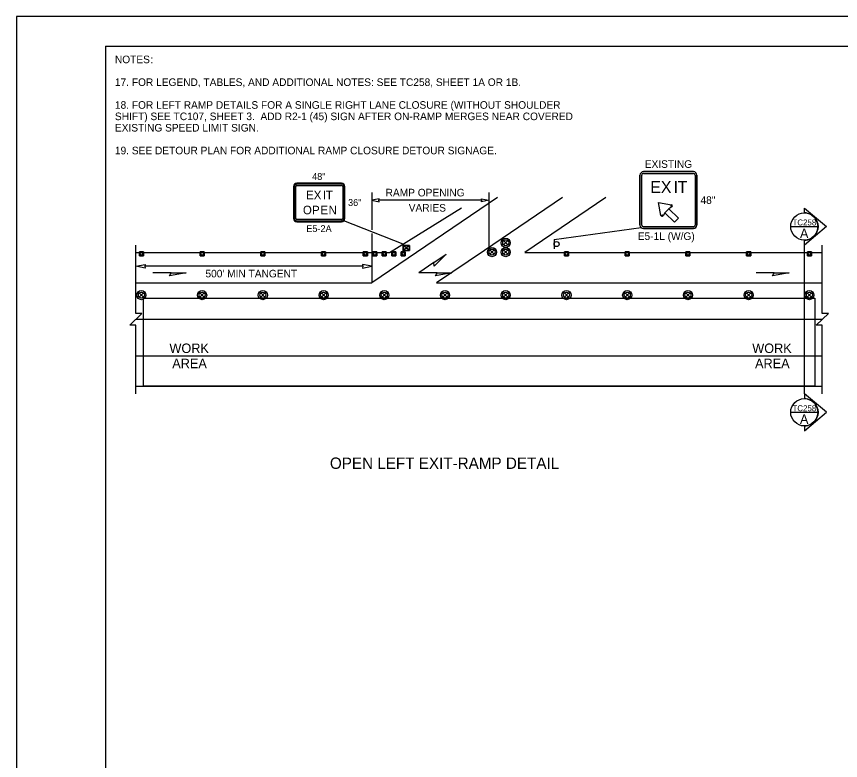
# Model space of a CAD drawing. Extents: x 99999 to 100116, y 99995 to 100013.
# Drawn here: x 100079.06 to 100087.75, y 100002.85 to 100010.69 of the extents above; entities that cross this region are included whole.
import ezdxf

# ---------------------------------------------------------------- set-up
doc = ezdxf.new("R2010")
doc.units = 0
for name, color, linetype in [('RD_MK_LineEdgeYellow', 7, 'Continuous'), ('RD_MK_LineLane', 7, 'Continuous'), ('SH_DE_DetailHeading2Text', 7, 'Continuous'), ('SH_GI_GeneralNotesBodyText', 7, 'Continuous'), ('SH_GI_PlotLimits', 7, 'Continuous'), ('SH_GI_SectionCut', 7, 'Continuous'), ('SH_GI_SheetBorder', 7, 'Continuous'), ('TR_SN_ConstructionSigns', 7, 'Continuous'), ('TR_WZ_PortableSignMount5ftMinBlk-Org', 7, 'Continuous'), ('TR_WZ_TrafficCone', 7, 'Continuous'), ('TR_WZ_TrafficSafetyDrum', 7, 'Continuous'), ('TR_WZ_WorkAreaLabel', 7, 'Continuous'), ('TR_WZ_WorkZoneDetails', 7, 'Continuous'), ('TR_WZ_WorkZoneTextCurrent', 7, 'Continuous')]:
    doc.layers.add(name, color=color, linetype=linetype)

msp = doc.modelspace()

# ---------------------------------------------------------------- linework, layer by layer
at = {"layer": 'RD_MK_LineEdgeYellow'}
for p, q in [((100084.1333, 100008.7784), (100082.8064, 100007.8789)), ((100080.32, 100007.8789), (100082.8064, 100007.8789)), ((100084.4209, 100007.8789), (100087.555, 100007.8789)), ((100080.32, 100007.1109), (100087.555, 100007.1109))]:
    msp.add_line(p, q, dxfattribs=at)
at = {"layer": 'RD_MK_LineLane'}
msp.add_lwpolyline([(100087.555, 100007.4949), (100080.32, 100007.4949)], dxfattribs=at)
at = {"layer": 'SH_GI_PlotLimits'}
msp.add_lwpolyline([(100079.0625, 99999.6875), (100096.0625, 99999.6875), (100096.0625, 100010.6875), (100079.0625, 100010.6875)], close=True, dxfattribs=at)
at = {"layer": 'SH_GI_SectionCut'}
for p, q in [((100087.3657, 100008.6178), (100087.3657, 100008.6687)), ((100087.3657, 100008.6687), (100087.5983, 100008.4738)), ((100087.5983, 100008.4738), (100087.3657, 100008.2789)), ((100087.3657, 100008.2789), (100087.3657, 100008.3298)), ((100087.3657, 100006.7109), (100087.3657, 100008.2789)), ((100087.3657, 100006.7109), (100087.3657, 100006.66)), ((100087.5983, 100006.516), (100087.3657, 100006.7109)), ((100087.3657, 100006.3211), (100087.5983, 100006.516)), ((100087.3657, 100006.372), (100087.3657, 100006.3211))]:
    msp.add_line(p, q, dxfattribs=at)
for points in [[(100087.2217, 100008.4738), (100087.5097, 100008.4738)], [(100087.2217, 100006.516), (100087.5097, 100006.516)]]:
    msp.add_lwpolyline(points, dxfattribs=at)
for centre in [(100087.3657, 100008.4738), (100087.3657, 100006.516)]:
    msp.add_circle(centre, 0.144, dxfattribs=at)
for centre in [(100087.3657, 100008.4738), (100087.3657, 100006.516)]:
    msp.add_arc(centre, 0.144, 269.99779, 90.00221, dxfattribs=at)
at = {"layer": 'SH_GI_SheetBorder'}
for q in [(100080, 100000), (100095.75, 100010.375)]:
    msp.add_line((100080, 100010.375), q, dxfattribs=at)
at = {"layer": 'TR_SN_ConstructionSigns'}
for p, q in [((100085.6712, 100009.0522), (100086.1962, 100009.0522)), ((100086.1962, 100009.0522), (100085.6712, 100009.0522)), ((100086.1962, 100009.0522), (100085.6712, 100009.0522)), ((100086.1962, 100009.0522), (100085.6712, 100009.0522)), ((100086.1962, 100009.0522), (100085.6712, 100009.0522)), ((100085.6712, 100009.0335), (100086.1962, 100009.0335)), ((100086.1962, 100009.0522), (100086.1962, 100009.0522)), ((100085.6337, 100008.4897), (100085.6337, 100009.0147)), ((100085.6337, 100009.0147), (100085.6337, 100009.0147)), ((100085.6337, 100009.0147), (100085.6337, 100008.4897)), ((100085.6337, 100009.0147), (100085.6337, 100008.4897)), ((100085.6337, 100009.0147), (100085.6337, 100008.4897)), ((100085.6337, 100009.0147), (100085.6337, 100008.4897)), ((100085.6525, 100008.4897), (100085.6525, 100009.0147)), ((100086.215, 100009.0147), (100086.215, 100008.4897)), ((100086.2337, 100009.0147), (100086.2337, 100008.4897)), ((100086.2337, 100008.4897), (100086.2337, 100009.0147)), ((100086.2337, 100008.4897), (100086.2337, 100009.0147)), ((100086.2337, 100008.4897), (100086.2337, 100009.0147)), ((100086.2337, 100008.4897), (100086.2337, 100009.0147)), ((100081.983, 100008.8955), (100081.983, 100008.558)), ((100081.9914, 100008.8955), (100081.9914, 100008.558)), ((100082.0055, 100008.558), (100082.0055, 100008.8955)), ((100082.4893, 100008.9292), (100082.0168, 100008.9292)), ((100082.4893, 100008.9208), (100082.0168, 100008.9208)), ((100082.0168, 100008.9067), (100082.4893, 100008.9067)), ((100082.5005, 100008.8955), (100082.5005, 100008.558)), ((100082.5146, 100008.558), (100082.5146, 100008.8955)), ((100082.523, 100008.558), (100082.523, 100008.8955)), ((100085.8293, 100008.7277), (100085.9652, 100008.7029)), ((100085.8541, 100008.5918), (100085.8293, 100008.7277)), ((100085.9688, 100008.68), (100085.9376, 100008.6614)), ((100085.9652, 100008.7029), (100085.9624, 100008.6907)), ((100085.9624, 100008.6907), (100085.9652, 100008.7029)), ((100085.9624, 100008.6907), (100085.9688, 100008.68)), ((100085.9688, 100008.68), (100085.9624, 100008.6907)), ((100085.8663, 100008.5946), (100085.8541, 100008.5918)), ((100085.8541, 100008.5918), (100085.8663, 100008.5946)), ((100085.8771, 100008.5882), (100085.8663, 100008.5946)), ((100085.8663, 100008.5946), (100085.8771, 100008.5882)), ((100085.8956, 100008.6195), (100085.8771, 100008.5882)), ((100085.8956, 100008.6195), (100085.9376, 100008.6614)), ((100085.9376, 100008.6614), (100085.8956, 100008.6195)), ((100085.9961, 100008.5189), (100085.8956, 100008.6195)), ((100085.9376, 100008.6614), (100086.0381, 100008.5609)), ((100082.4893, 100008.5467), (100082.0168, 100008.5467)), ((100082.0168, 100008.5327), (100082.4893, 100008.5327)), ((100082.0168, 100008.5242), (100082.4893, 100008.5242)), ((100086.0381, 100008.5609), (100085.9961, 100008.5189)), ((100086.1962, 100008.471), (100085.6712, 100008.471)), ((100086.1962, 100008.4522), (100085.6712, 100008.4522)), ((100085.6712, 100008.4522), (100085.6712, 100008.4522)), ((100085.6712, 100008.4522), (100086.1962, 100008.4522)), ((100085.6712, 100008.4522), (100086.1962, 100008.4522)), ((100085.6712, 100008.4522), (100086.1962, 100008.4522)), ((100086.2337, 100008.4897), (100086.2337, 100008.4897))]:
    msp.add_line(p, q, dxfattribs=at)
for points in [[(100085.6712, 100008.4522), (100085.6712, 100008.4522)], [(100085.6712, 100008.4522), (100086.1962, 100008.4522), (100086.1962, 100008.4522)]]:
    msp.add_lwpolyline(points, dxfattribs=at)
for centre, radius, start, end in [((100085.6712, 100009.0147), 0.0375, 90, 180.00001), ((100085.6712, 100009.0147), 0.0375, 90, 180), ((100085.6712, 100009.0147), 0.0375, 90, 180), ((100085.6712, 100009.0147), 0.0375, 90, 180), ((100085.6712, 100009.0147), 0.0375, 90, 180), ((100085.6712, 100009.0147), 0.0187, 90, 180.00001), ((100086.1962, 100009.0147), 0.0375, 0, 90), ((100086.1962, 100009.0147), 0.0375, 0, 90), ((100086.1962, 100009.0147), 0.0375, 0, 90), ((100086.1962, 100009.0147), 0.0375, 0, 90), ((100086.1962, 100009.0147), 0.0375, 0, 90), ((100086.1962, 100009.0147), 0.0187, 0, 90), ((100082.0168, 100008.8955), 0.0338, 90, 180), ((100082.0168, 100008.8955), 0.0253, 90, 180.00001), ((100082.0168, 100008.8955), 0.0112, 90, 180.00001), ((100082.4893, 100008.8955), 0.0338, 360, 90), ((100082.4893, 100008.8955), 0.0253, 360, 90), ((100082.4893, 100008.8955), 0.0112, 360, 90), ((100085.9624, 100008.6907), 0.0125, 300.67412, 77.22876), ((100085.8663, 100008.5946), 0.0125, 192.77123, 329.32586), ((100082.0168, 100008.558), 0.0338, 180, 270.00001), ((100082.0168, 100008.558), 0.0253, 180.00001, 270), ((100082.0168, 100008.558), 0.0112, 180.00001, 270), ((100082.4893, 100008.558), 0.0338, 270.00001, 0.00001), ((100082.4893, 100008.558), 0.0253, 270, 0.00001), ((100082.4893, 100008.558), 0.0112, 270, 0.00001), ((100085.6712, 100008.4897), 0.0375, 180.00001, 270), ((100085.6712, 100008.4897), 0.0375, 180, 270.00001), ((100085.6712, 100008.4897), 0.0375, 180, 270.00001), ((100085.6712, 100008.4897), 0.0375, 180, 270), ((100085.6712, 100008.4897), 0.0375, 180, 270.00001), ((100085.6712, 100008.4897), 0.0187, 180.00001, 270), ((100086.1962, 100008.4897), 0.0375, 270, 0.00001), ((100086.1962, 100008.4897), 0.0375, 270.00001, 0.00001), ((100086.1962, 100008.4897), 0.0375, 270.00001, 0.00001), ((100086.1962, 100008.4897), 0.0375, 270.00001, 0.00001), ((100086.1962, 100008.4897), 0.0187, 270, 0.00001), ((100086.1962, 100008.4897), 0.0375, 270.00001, 0.00001)]:
    msp.add_arc(centre, radius, start, end, dxfattribs=at)
at = {"layer": 'TR_WZ_PortableSignMount5ftMinBlk-Org'}
for p, q in [((100083.1389, 100008.2069), (100083.1389, 100008.2869)), ((100083.2056, 100008.2729), (100083.1389, 100008.2209)), ((100083.2056, 100008.2209), (100083.1389, 100008.2729)), ((100083.1723, 100008.2469), (100083.1723, 100008.2469)), ((100083.1724, 100008.247), (100083.1724, 100008.247))]:
    msp.add_line(p, q, dxfattribs=at)
for points in [[(100083.2056, 100008.2729), (100083.2056, 100008.2209), (100083.1389, 100008.2209), (100083.1389, 100008.2729)], [(100083.1389, 100008.2209), (100083.2056, 100008.2209), (100083.2056, 100008.2729), (100083.1389, 100008.2729)]]:
    msp.add_lwpolyline(points, close=True, dxfattribs=at)
at = {"layer": 'TR_WZ_TrafficCone'}
for points in [[(100080.3576, 100008.1642), (100080.4003, 100008.1642), (100080.4003, 100008.2069), (100080.3576, 100008.2069), (100080.3576, 100008.1642)], [(100080.3576, 100008.2069), (100080.4003, 100008.2069), (100080.4003, 100008.1642), (100080.3576, 100008.1642), (100080.3576, 100008.2069)], [(100080.9976, 100008.1642), (100081.0403, 100008.1642), (100081.0403, 100008.2069), (100080.9976, 100008.2069), (100080.9976, 100008.1642)], [(100080.9976, 100008.2069), (100081.0403, 100008.2069), (100081.0403, 100008.1642), (100080.9976, 100008.1642), (100080.9976, 100008.2069)], [(100081.6376, 100008.1642), (100081.6803, 100008.1642), (100081.6803, 100008.2069), (100081.6376, 100008.2069), (100081.6376, 100008.1642)], [(100081.6376, 100008.2069), (100081.6803, 100008.2069), (100081.6803, 100008.1642), (100081.6376, 100008.1642), (100081.6376, 100008.2069)], [(100082.2776, 100008.1642), (100082.3203, 100008.1642), (100082.3203, 100008.2069), (100082.2776, 100008.2069), (100082.2776, 100008.1642)], [(100082.2776, 100008.2069), (100082.3203, 100008.2069), (100082.3203, 100008.1642), (100082.2776, 100008.1642), (100082.2776, 100008.2069)], [(100082.7176, 100008.1642), (100082.7603, 100008.1642), (100082.7603, 100008.2069), (100082.7176, 100008.2069), (100082.7176, 100008.1642)], [(100082.7176, 100008.2069), (100082.7603, 100008.2069), (100082.7603, 100008.1642), (100082.7176, 100008.1642), (100082.7176, 100008.2069)], [(100082.8176, 100008.1642), (100082.8603, 100008.1642), (100082.8603, 100008.2069), (100082.8176, 100008.2069), (100082.8176, 100008.1642)], [(100082.8176, 100008.2069), (100082.8603, 100008.2069), (100082.8603, 100008.1642), (100082.8176, 100008.1642), (100082.8176, 100008.2069)], [(100082.9176, 100008.1642), (100082.9603, 100008.1642), (100082.9603, 100008.2069), (100082.9176, 100008.2069), (100082.9176, 100008.1642)], [(100082.9176, 100008.2069), (100082.9603, 100008.2069), (100082.9603, 100008.1642), (100082.9176, 100008.1642), (100082.9176, 100008.2069)], [(100083.0176, 100008.1642), (100083.0603, 100008.1642), (100083.0603, 100008.2069), (100083.0176, 100008.2069), (100083.0176, 100008.1642)], [(100083.0176, 100008.2069), (100083.0603, 100008.2069), (100083.0603, 100008.1642), (100083.0176, 100008.1642), (100083.0176, 100008.2069)], [(100083.1176, 100008.1642), (100083.1603, 100008.1642), (100083.1603, 100008.2069), (100083.1176, 100008.2069), (100083.1176, 100008.1642)], [(100083.1176, 100008.2069), (100083.1603, 100008.2069), (100083.1603, 100008.1642), (100083.1176, 100008.1642), (100083.1176, 100008.2069)], [(100084.8376, 100008.1642), (100084.8803, 100008.1642), (100084.8803, 100008.2069), (100084.8376, 100008.2069), (100084.8376, 100008.1642)], [(100084.8376, 100008.2069), (100084.8803, 100008.2069), (100084.8803, 100008.1642), (100084.8376, 100008.1642), (100084.8376, 100008.2069)], [(100085.4776, 100008.1642), (100085.5203, 100008.1642), (100085.5203, 100008.2069), (100085.4776, 100008.2069), (100085.4776, 100008.1642)], [(100085.4776, 100008.2069), (100085.5203, 100008.2069), (100085.5203, 100008.1642), (100085.4776, 100008.1642), (100085.4776, 100008.2069)], [(100086.1176, 100008.1642), (100086.1603, 100008.1642), (100086.1603, 100008.2069), (100086.1176, 100008.2069), (100086.1176, 100008.1642)], [(100086.1176, 100008.2069), (100086.1603, 100008.2069), (100086.1603, 100008.1642), (100086.1176, 100008.1642), (100086.1176, 100008.2069)], [(100086.7576, 100008.1642), (100086.8003, 100008.1642), (100086.8003, 100008.2069), (100086.7576, 100008.2069), (100086.7576, 100008.1642)], [(100086.7576, 100008.2069), (100086.8003, 100008.2069), (100086.8003, 100008.1642), (100086.7576, 100008.1642), (100086.7576, 100008.2069)], [(100087.3976, 100008.1642), (100087.4403, 100008.1642), (100087.4403, 100008.2069), (100087.3976, 100008.2069), (100087.3976, 100008.1642)], [(100087.3976, 100008.2069), (100087.4403, 100008.2069), (100087.4403, 100008.1642), (100087.3976, 100008.1642), (100087.3976, 100008.2069)]]:
    msp.add_lwpolyline(points, dxfattribs=at)
for centre in [(100080.3789, 100008.1856), (100081.0189, 100008.1856), (100081.6589, 100008.1856), (100082.2989, 100008.1856), (100082.7389, 100008.1856), (100082.8389, 100008.1856), (100082.9389, 100008.1856), (100083.0389, 100008.1856), (100083.1389, 100008.1856), (100084.8589, 100008.1856), (100085.4989, 100008.1856), (100086.1389, 100008.1856), (100086.7789, 100008.1856), (100087.4189, 100008.1856)]:
    msp.add_circle(centre, 0.0133, dxfattribs=at)
at = {"layer": 'TR_WZ_TrafficSafetyDrum'}
for p, q in [((100084.1963, 100008.3252), (100084.2415, 100008.2799)), ((100084.2415, 100008.3252), (100084.1963, 100008.2799)), ((100084.0513, 100008.2269), (100084.0965, 100008.1816)), ((100084.0965, 100008.2269), (100084.0513, 100008.1816)), ((100084.1963, 100008.2269), (100084.2415, 100008.1816)), ((100084.2415, 100008.2269), (100084.1963, 100008.1816)), ((100080.3563, 100007.7735), (100080.4015, 100007.7283)), ((100080.4015, 100007.7735), (100080.3563, 100007.7283)), ((100080.9963, 100007.7735), (100081.0415, 100007.7283)), ((100081.0415, 100007.7735), (100080.9963, 100007.7283)), ((100081.6363, 100007.7735), (100081.6815, 100007.7283)), ((100081.6815, 100007.7735), (100081.6363, 100007.7283)), ((100082.2763, 100007.7735), (100082.3215, 100007.7283)), ((100082.3215, 100007.7735), (100082.2763, 100007.7283)), ((100082.9163, 100007.7735), (100082.9615, 100007.7283)), ((100082.9615, 100007.7735), (100082.9163, 100007.7283)), ((100083.5563, 100007.7735), (100083.6015, 100007.7283)), ((100083.6015, 100007.7735), (100083.5563, 100007.7283)), ((100084.1963, 100007.7735), (100084.2415, 100007.7283)), ((100084.2415, 100007.7735), (100084.1963, 100007.7283)), ((100084.8363, 100007.7735), (100084.8815, 100007.7283)), ((100084.8815, 100007.7735), (100084.8363, 100007.7283)), ((100085.4763, 100007.7735), (100085.5215, 100007.7283)), ((100085.5215, 100007.7735), (100085.4763, 100007.7283)), ((100086.1163, 100007.7735), (100086.1615, 100007.7283)), ((100086.1615, 100007.7735), (100086.1163, 100007.7283)), ((100086.7563, 100007.7735), (100086.8015, 100007.7283)), ((100086.8015, 100007.7735), (100086.7563, 100007.7283)), ((100087.3963, 100007.7735), (100087.4415, 100007.7283)), ((100087.4415, 100007.7735), (100087.3963, 100007.7283))]:
    msp.add_line(p, q, dxfattribs=at)
for centre, radius in [((100084.2189, 100008.3025), 0.048), ((100084.2189, 100008.3025), 0.048), ((100084.2189, 100008.3025), 0.032), ((100084.0739, 100008.2042), 0.048), ((100084.0739, 100008.2042), 0.048), ((100084.2189, 100008.2042), 0.048), ((100084.2189, 100008.2042), 0.048), ((100084.0739, 100008.2042), 0.032), ((100084.2189, 100008.2042), 0.032), ((100080.3789, 100007.7509), 0.048), ((100080.3789, 100007.7509), 0.048), ((100080.3789, 100007.7509), 0.032), ((100081.0189, 100007.7509), 0.048), ((100081.0189, 100007.7509), 0.048), ((100081.0189, 100007.7509), 0.032), ((100081.6589, 100007.7509), 0.048), ((100081.6589, 100007.7509), 0.048), ((100081.6589, 100007.7509), 0.032), ((100082.2989, 100007.7509), 0.048), ((100082.2989, 100007.7509), 0.048), ((100082.2989, 100007.7509), 0.032), ((100082.9389, 100007.7509), 0.048), ((100082.9389, 100007.7509), 0.048), ((100082.9389, 100007.7509), 0.032), ((100083.5789, 100007.7509), 0.048), ((100083.5789, 100007.7509), 0.048), ((100083.5789, 100007.7509), 0.032), ((100084.2189, 100007.7509), 0.048), ((100084.2189, 100007.7509), 0.048), ((100084.2189, 100007.7509), 0.032), ((100084.8589, 100007.7509), 0.048), ((100084.8589, 100007.7509), 0.048), ((100084.8589, 100007.7509), 0.032), ((100085.4989, 100007.7509), 0.048), ((100085.4989, 100007.7509), 0.048), ((100085.4989, 100007.7509), 0.032), ((100086.1389, 100007.7509), 0.048), ((100086.1389, 100007.7509), 0.048), ((100086.1389, 100007.7509), 0.032), ((100086.7789, 100007.7509), 0.048), ((100086.7789, 100007.7509), 0.048), ((100086.7789, 100007.7509), 0.032), ((100087.4189, 100007.7509), 0.048), ((100087.4189, 100007.7509), 0.048), ((100087.4189, 100007.7509), 0.032)]:
    msp.add_circle(centre, radius, dxfattribs=at)
at = {"layer": 'TR_WZ_WorkZoneDetails'}
for p, q in [((100082.8064, 100008.8313), (100082.8064, 100008.4391)), ((100084.8178, 100008.7784), (100083.9935, 100008.2196)), ((100084.0419, 100008.8313), (100084.0419, 100008.1936)), ((100085.2753, 100008.7784), (100084.4209, 100008.1989)), ((100083.9669, 100008.7513), (100082.8814, 100008.7513)), ((100082.9928, 100008.1989), (100083.7508, 100008.6713)), ((100083.1389, 100008.2869), (100082.5131, 100008.5341)), ((100084.7282, 100008.3389), (100085.6447, 100008.4632)), ((100082.8064, 100008.3991), (100082.8064, 100007.8789)), ((100084.7282, 100008.3389), (100084.7282, 100008.2389)), ((100080.32, 100008.1989), (100082.9928, 100008.1989)), ((100083.9935, 100008.2196), (100083.4908, 100007.8789)), ((100084.4209, 100008.1989), (100087.555, 100008.1989)), ((100083.4618, 100008.0932), (100083.3021, 100007.985)), ((100082.7126, 100008.0559), (100080.4137, 100008.0559)), ((100080.6926, 100007.985), (100080.4997, 100007.985)), ((100083.495, 100007.985), (100083.3021, 100007.985)), ((100087.0492, 100007.985), (100086.8563, 100007.985)), ((100083.4908, 100007.8789), (100084.4209, 100007.8789)), ((100080.32, 100006.7909), (100087.555, 100006.7909))]:
    msp.add_line(p, q, dxfattribs=at)
for points in [[(100082.8064, 100008.7513), (100082.885, 100008.7359), (100082.8814, 100008.7513), (100082.885, 100008.7667)], [(100084.0419, 100008.7513), (100083.9633, 100008.7359), (100083.9669, 100008.7513), (100083.9633, 100008.7667)], [(100083.592, 100008.1814), (100083.4644, 100008.0577), (100083.4618, 100008.0932)], [(100080.32, 100008.0559), (100080.4183, 100008.0751), (100080.4137, 100008.0559), (100080.4183, 100008.0366)], [(100082.8063, 100008.0559), (100082.7081, 100008.0751), (100082.7126, 100008.0559), (100082.7081, 100008.0366)], [(100080.8498, 100007.985), (100080.6747, 100007.9541), (100080.6926, 100007.985)], [(100083.6523, 100007.985), (100083.4772, 100007.9541), (100083.495, 100007.985)], [(100087.2065, 100007.985), (100087.0314, 100007.9541), (100087.0492, 100007.985)], [(100080.4, 100006.7909), (100080.4, 100007.7189), (100087.475, 100007.7189), (100087.475, 100006.7909)]]:
    msp.add_lwpolyline(points, close=True, dxfattribs=at)
for points in [[(100080.32, 100006.7109), (100080.32, 100007.433), (100080.256, 100007.433), (100080.384, 100007.5569), (100080.32, 100007.5569), (100080.32, 100008.2789)], [(100087.555, 100006.7109), (100087.555, 100007.433), (100087.491, 100007.433), (100087.619, 100007.5569), (100087.555, 100007.5569), (100087.555, 100008.2789)]]:
    msp.add_lwpolyline(points, dxfattribs=at)
msp.add_circle((100084.7552, 100008.2888), 0.027, dxfattribs=at)
msp.add_circle((100084.7552, 100008.2888), 0.027, dxfattribs=at)

# ---------------------------------------------------------------- texts
at = {"layer": 'SH_DE_DetailHeading2Text'}
msp.add_text('OPEN LEFT EXIT-RAMP DETAIL', height=0.12, rotation=360, dxfattribs=at).set_placement((100082.3657, 100005.9196))
at = {"layer": 'SH_GI_GeneralNotesBodyText'}
for s, p in [('NOTES', (100080.1, 100010.195)), (':', (100080.4743, 100010.195)), ('17. FOR LEGEND, TABLES, AND ADDITIONAL NOTES: SEE TC258, SHEET 1A OR 1B.', (100080.1, 100009.955)), ('18. FOR LEFT RAMP DETAILS FOR A SINGLE RIGHT LANE CLOSURE (WITHOUT SHOULDER ', (100080.1, 100009.715)), ('SHIFT) SEE TC107, SHEET 3.  ADD R2-1 (45) SIGN AFTER ON-RAMP MERGES NEAR COVERED ', (100080.1, 100009.595)), ('EXISTING SPEED LIMIT SIGN.', (100080.1, 100009.475)), ('19. SEE DETOUR PLAN FOR ADDITIONAL RAMP CLOSURE DETOUR SIGNAGE.', (100080.1, 100009.235))]:
    msp.add_text(s, height=0.08, rotation=360, dxfattribs=at).set_placement(p)
at = {"layer": 'SH_GI_SectionCut'}
for p in [(100087.2408, 100008.4854), (100087.2408, 100006.5276)]:
    msp.add_text('TC258', height=0.0625, dxfattribs=at).set_placement(p)
for p in [(100087.3195, 100008.3518), (100087.3195, 100006.394)]:
    msp.add_text('A', height=0.1, rotation=359.99005, dxfattribs=at).set_placement(p)
at = {"layer": 'TR_SN_ConstructionSigns'}
for s, height, p in [('EXISTING', 0.08, (100085.6839, 100009.0922)), ('48"', 0.072, (100082.1782, 100008.9652)), ('E', 0.09, (100082.1153, 100008.7605)), ('X', 0.09, (100082.1954, 100008.7605)), ('I', 0.09, (100082.2917, 100008.7605)), ('T', 0.09, (100082.3232, 100008.7605)), ('36"', 0.072, (100082.5568, 100008.6907)), ('48"', 0.08, (100086.2713, 100008.7122)), ('O', 0.09, (100082.0816, 100008.603)), ('P', 0.09, (100082.1779, 100008.603)), ('E', 0.09, (100082.2661, 100008.603)), ('N', 0.09, (100082.3516, 100008.603)), ('E5-2A', 0.072, (100082.1164, 100008.4162)), ('E5-1L (W/G)', 0.08, (100085.6101, 100008.3322))]:
    msp.add_text(s, height=height, rotation=360, dxfattribs=at).set_placement(p)
for s, p in [('E', (100085.7425, 100008.8277)), ('X', (100085.8537, 100008.8277)), ('I', (100085.9875, 100008.8277)), ('T', (100086.0312, 100008.8277))]:
    msp.add_text(s, height=0.125, dxfattribs=at).set_placement(p)
at = {"layer": 'TR_WZ_WorkAreaLabel'}
for s, p in [('WORK', (100080.6746, 100007.1409)), ('WORK', (100086.8169, 100007.1409)), ('AREA', (100080.7043, 100006.9809)), ('AREA', (100086.8465, 100006.9809))]:
    msp.add_text(s, height=0.1, dxfattribs=at).set_placement(p)
at = {"layer": 'TR_WZ_WorkZoneTextCurrent'}
for s, p in [('RAMP OPENING', (100082.9527, 100008.7913)), ('VARIES', (100083.1965, 100008.6313)), ("500' MIN TANGENT", (100081.0542, 100007.9379))]:
    msp.add_text(s, height=0.08, dxfattribs=at).set_placement(p)

doc.saveas('drawing.dxf')
